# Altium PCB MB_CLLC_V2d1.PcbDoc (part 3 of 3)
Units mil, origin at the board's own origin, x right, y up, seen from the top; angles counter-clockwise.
Board outline 9000 x 7000 mil, 2 copper layers (Top Layer, Bottom Layer); 436 components, 223 nets, 1335 pads, 200 vias.
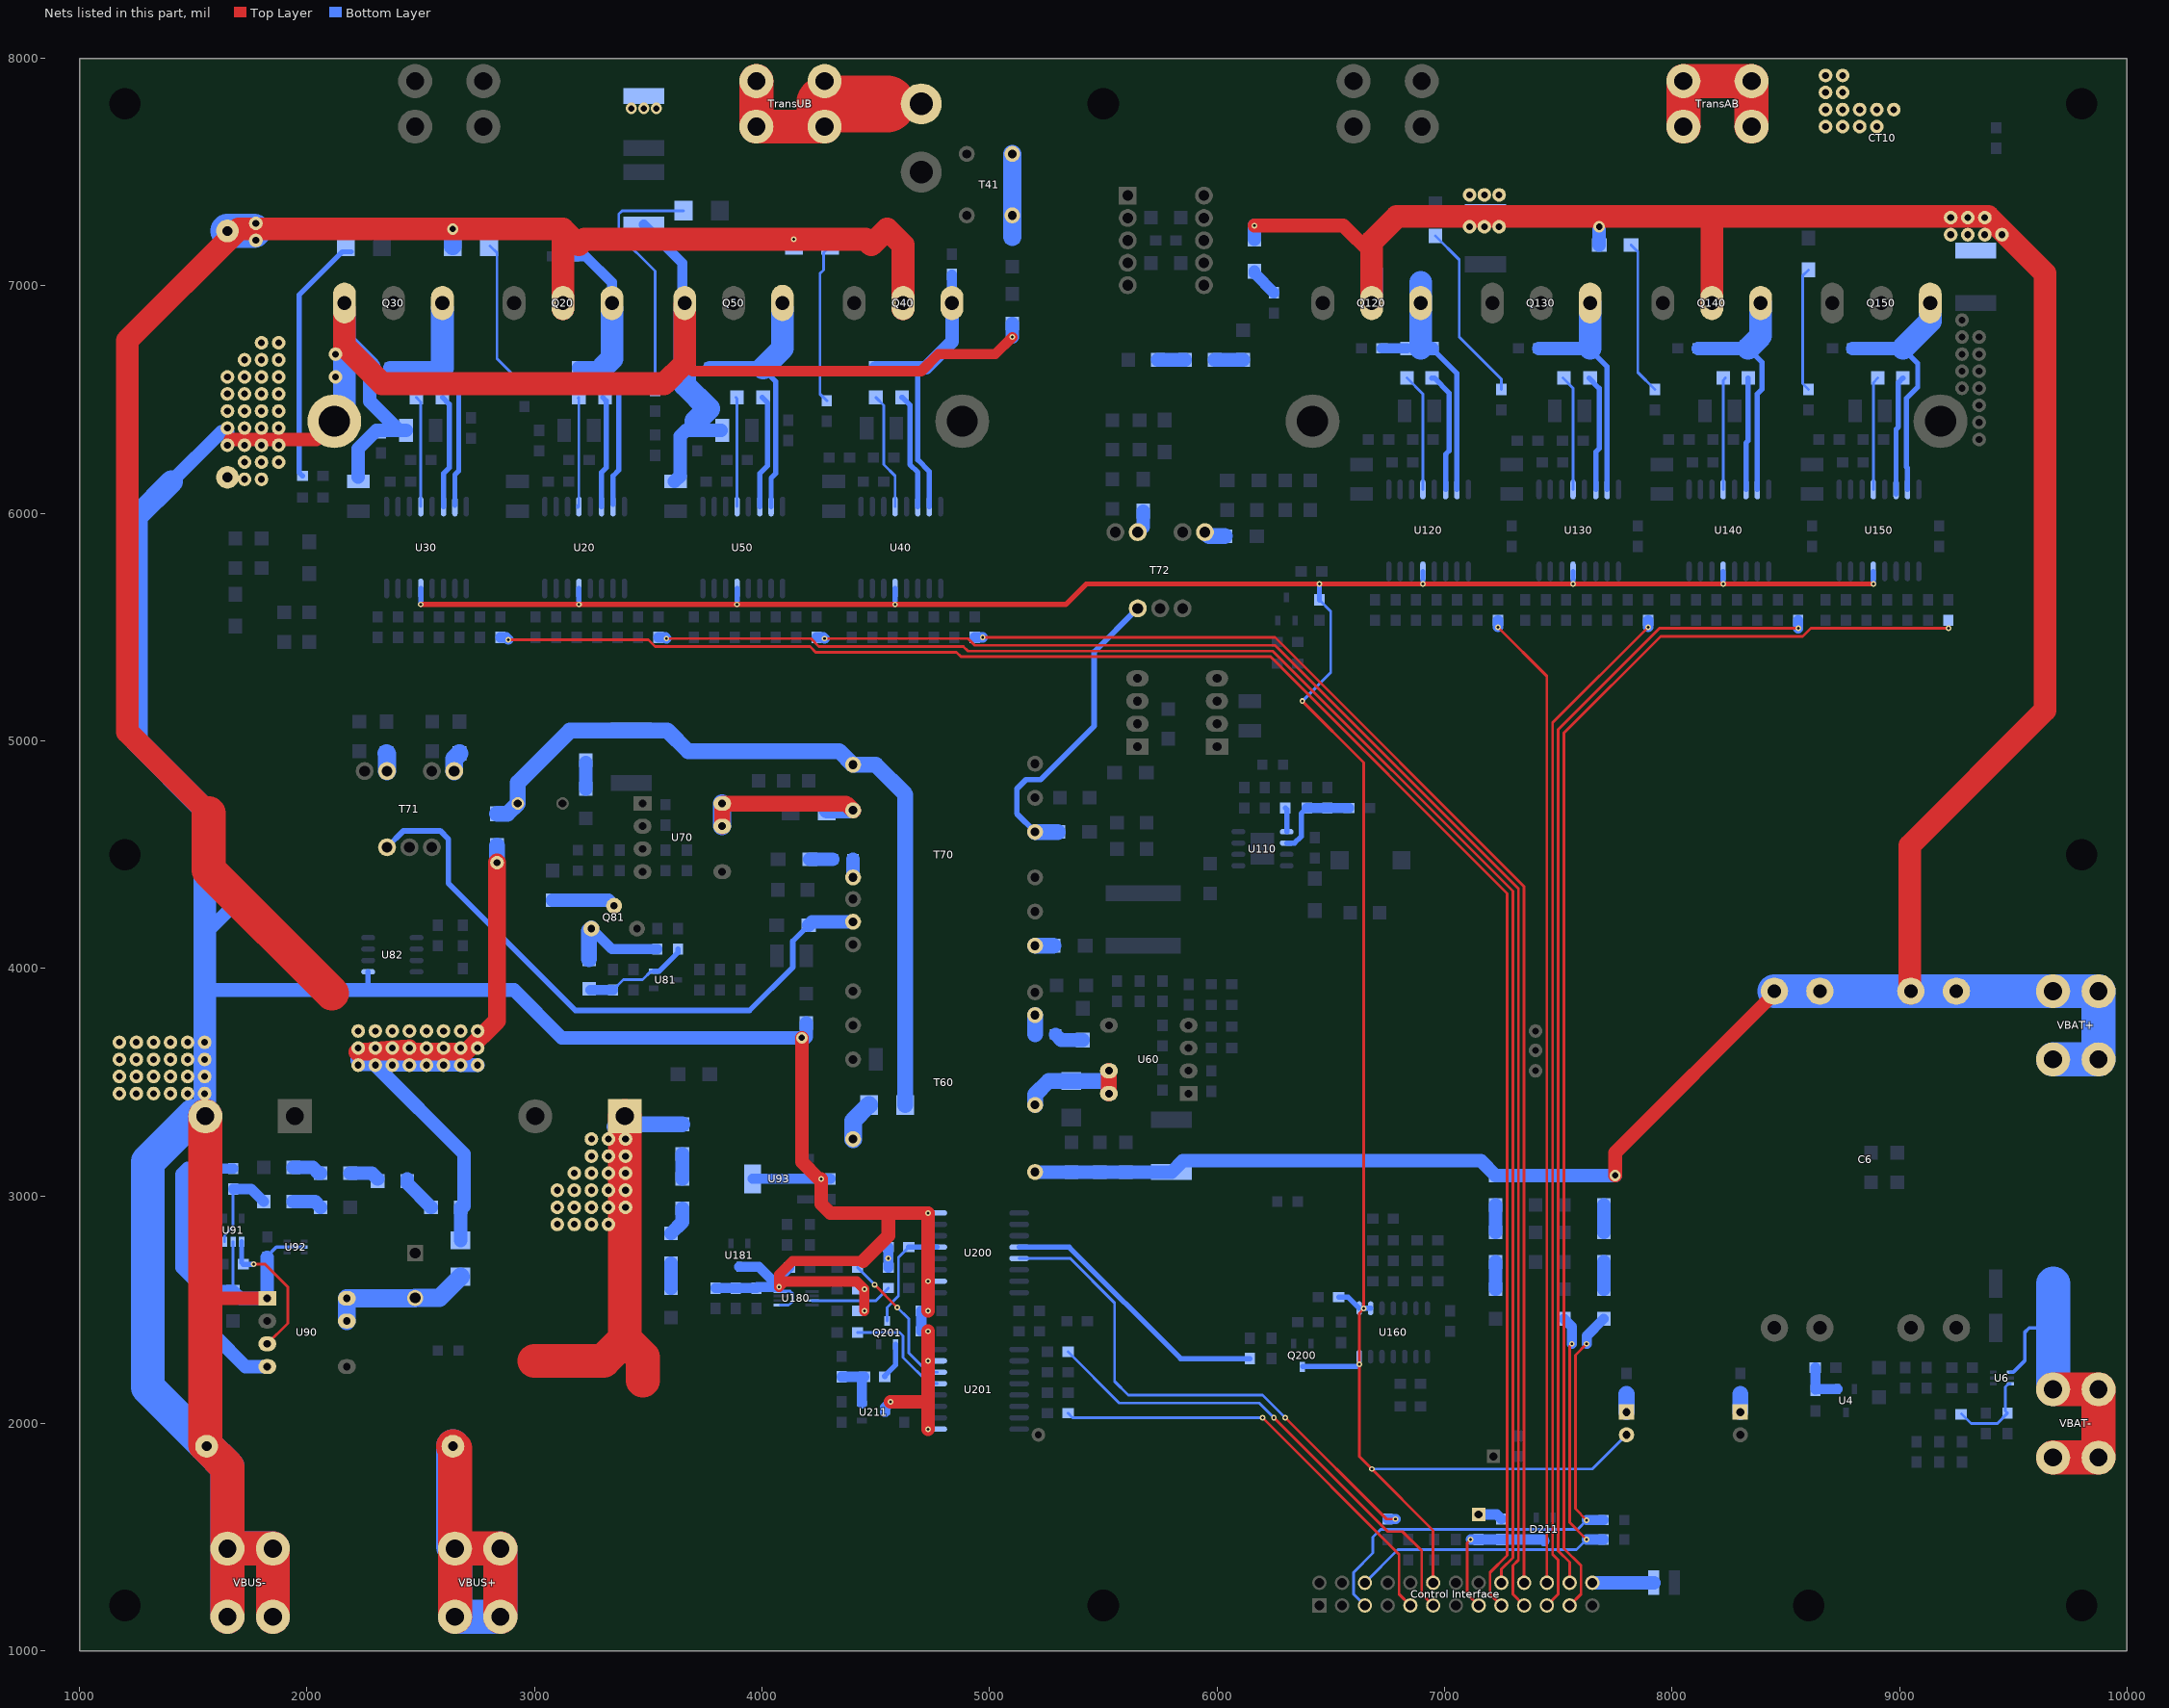
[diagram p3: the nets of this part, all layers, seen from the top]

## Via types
v1: diameter 25, hole 12, Top Layer to Bottom Layer, 169 vias
v2: diameter 50, hole 28, Top Layer to Bottom Layer, 31 vias

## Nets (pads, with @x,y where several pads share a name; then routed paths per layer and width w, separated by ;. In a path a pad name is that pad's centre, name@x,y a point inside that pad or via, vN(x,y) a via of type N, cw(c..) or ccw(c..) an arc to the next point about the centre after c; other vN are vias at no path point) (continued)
"NetControl Interface_5": "Control Interface.5" D191.1 R197.1 | length 2359.5
  Top Layer w12: v1(7625,1575) 7575,1625 7575,2300 v1(7625,2350)
  Bottom Layer w12: 6650,1200 6600,1250 6600,1345 6685,1430 6685,1500 6720,1535 7585,1535 v1(7625,1575)
  Bottom Layer w45: v1(7625,1575) D191.1@7700,1575 ; v1(7625,2350) 7625,2385 R197.1@7700,2460
"NetControl Interface_6": "Control Interface.6" D192.1 R262.1 | length 2148.4
  Top Layer w12: v1(7560,2350) 7550,2340 7550,1565 v1(7625,1490)
  Bottom Layer w12: 6650,1300 6795,1445 7580,1445 v1(7625,1490)
  Bottom Layer w45: R262.1@7525,2460 7560,2425 v1(7560,2350) ; v1(7625,1490) D192.1@7700,1490
"NetControl Interface_9": "Control Interface.9" R202.2 | length 1962.5
  Top Layer w12: v1(6200,2025) 6800,1425 6800,1250 6850,1200
  Bottom Layer w12: R202.2@5345,2045 5365,2025 v1(6200,2025) v1@6205,2025
"NetControl Interface_11": "Control Interface.11" R208.2 | length 2178.1
  Top Layer w12: v1(6250,2025) 6750,1525 6815,1525 6900,1440 6900,1250 6950,1200
  Bottom Layer w12: R208.2@5345,2315 5570,2090 6185,2090 v1(6250,2025)
"NetControl Interface_12": "Control Interface.12" Fault.2 Q200.3 R165.2 R172.2 U20.13 U30.13 U40.13 U50.13 U120.13 U130.13 U140.13 U150.13 U160.1 U160.2 U160.14 | length 13220.1
  Top Layer w12: v1(6375,5175) 6645,4905 v1(6645,2505) 6625,2485 v1(6625,2260) 6625,1855 v1(6680,1800) 6950,1530 6950,1300
  Top Layer w23: v1(2500,5600) v1(3195,5600) v1(3890,5600) v1(4585,5600) 5335,5600 5425,5690 v1(6450,5690) v1(6905,5690) v1(7565,5690) v1(8225,5690) v1(8885,5690)
  Bottom Layer w12: Q200.3@6375,2248.82 Q200.3@6376.18,2250 ; v1(6375,5175) 6500,5300 6500,5570 R165.2@6450,5620 ; v1(6680,1800) 7650,1800 Fault.2@7800,1950
  Bottom Layer w23: v1(2500,5600) U30.13@2500,5670 ; v1(3195,5600) U20.13@3195,5670 ; v1(3890,5600) U50.13@3890,5670 ; v1(4585,5600) U40.13@4585,5670 ; Q200.3@6376.18,2250 6615,2250 v1(6625,2260) ; R165.2@6450,5620 v1(6450,5690) ; R172.2@6535,2555 6576.3,2555 U160.1@6625,2506.3 ; v1@6641.3,2506.3 U160.2@6675,2506.3 ; v1(6905,5690) U120.13@6905,5745 ; v1(7565,5690) U130.13@7565,5745 ; v1(8225,5690) U140.13@8225,5745 ; v1(8885,5690) U150.13@8885,5745
"NetControl Interface_15": "Control Interface.15" D211.3 R217.1 R219.2 | length 644.5
  Top Layer w12: v1(7115,1490) 7100,1475 7100,1250 7150,1200
  Bottom Layer w45: v1(7115,1490) R217.1@7150,1490 R219.2@7250,1490 7433.82,1490 D211.3@7440,1483.82
"NetControl Interface_17": "Control Interface.17" R36.2 | length 8072.8
  Top Layer w12: v1(2885,5445) 3500,5445 3530,5415 4211,5415 4236,5390 4855,5390 4875,5370 6235,5370 7275,4330 7275,1420 7200,1345 7200,1250 7250,1200
  Bottom Layer w45: R36.2@2850,5455 2875,5455 v1(2885,5445)
"NetControl Interface_18": "Control Interface.18" R26.2 | length 7277.6
  Top Layer w12: v1(3580,5450) 4215,5450 4250,5415 4885,5415 4905,5395 6245,5395 7300,4340 7300,1410 7250,1360 7250,1300
  Bottom Layer w45: R26.2@3545,5455 3575,5455 v1(3580,5450)
"NetControl Interface_19": "Control Interface.19" R56.2 | length 6723.8
  Top Layer w12: v1(4275,5450) 4905,5450 4935,5420 6255,5420 7325,4350 7325,1400 7300,1375 7300,1250 7350,1200
  Bottom Layer w45: R56.2@4240,5455 4270,5455 v1(4275,5450)
"NetControl Interface_20": "Control Interface.20" R46.2 | length 5928.6
  Top Layer w12: v1(4970,5455) 6255,5455 7350,4360 7350,1300
  Bottom Layer w45: R46.2@4935,5455 v1(4970,5455)
"NetControl Interface_21": "Control Interface.21" R136.2 | length 4535
  Top Layer w12: 7450,1200 7500,1250 7500,1400 7475,1425 7475,5080 v1(7895,5500)
  Bottom Layer w45: v1(7895,5500) R136.2@7895,5530
"NetControl Interface_22": "Control Interface.22" R126.2 | length 4319.1
  Top Layer w12: v1(7235,5500) 7450,5285 7450,1300
  Bottom Layer w45: v1(7235,5500) R126.2@7235,5530
"NetControl Interface_23": "Control Interface.23" R156.2 | length 5767.3
  Top Layer w12: 7550,1200 7600,1250 7600,1375 7525,1450 7525,5035 7950,5460 8575,5460 8610,5495 v1(9215,5495)
"NetControl Interface_24": "Control Interface.24" R146.2 | length 5045
  Top Layer w12: 7550,1300 7550,1390 7500,1440 7500,5050 7945,5495 v1(8555,5495)
  Bottom Layer w45: v1(8555,5495) R146.2@8555,5530
"NetControl Interface_26": "Control Interface.26" L190.1 | length 270
  Bottom Layer w60: 7650,1300 L190.1@7920,1300
NetCT10_11: CT10.11 pad.47@8675,7700 pad.47@8675,7775 pad.47@8675,7850 pad.47@8675,7925 pad.47@8750,7700 pad.47@8750,7775 pad.47@8750,7850 pad.47@8750,7925 pad.47@8825,7700 pad.47@8825,7775 pad.47@8900,7700 pad.47@8900,7775 pad.47@8975,7775 TransAB.1 | length 700
  Top Layer w150: TransAB.1@8050,7700 TransAB.1@8050,7900 TransAB.1@8350,7900 TransAB.1@8350,7700
NetCT20_11: pad.CT20A TransUB.1 | length 875
  Top Layer w150: TransUB.1@3975,7900 TransUB.1@3975,7700 TransUB.1@4275,7700 4275,7800
  Top Layer w250: 4275,7800 4550,7800
NetD20_1: D20.1 R20.1 | length 677.1
  Bottom Layer w12: D20.1@2805,7175 2835,7145 2835,6680 R20.1@2955,6560
NetD30_1: D30.1 R30.1 | length 1109.9
  Bottom Layer w23: R30.1@1980,6165 1965,6180 1965,6960 2155,7150 D30.1@2195,7150
NetD40_1: D40.1 R40.1 | length 711.1
  Bottom Layer w12: R40.1@4285,6495 4255,6525 4255,7055 4270,7070 4270,7145 D40.1@4300,7175
NetD50_1: D50.1 R50.1 | length 1132.5
  Bottom Layer w12: R50.1@3530,6540 3530,7065 3370,7225 3370,7315 3385,7330 D50.1@3655,7330
NetD60_1: D60.1 T60.4 U60.6 U60.7 | length 594.9
  Top Layer w70: U60.7@5525,3450 U60.6@5525,3550
  Bottom Layer w70: T60.4@5200,3400 5200,3445 5260,3505 D60.1@5360,3505 5525,3505 ; U60.7@5525,3450 5525,3505 ; U60.6@5525,3550 5525,3505
NetD63_1: D63.1 R63.2 | length 130.4
  Bottom Layer w60: R63.2@5290,3710 5315,3685 D63.1@5410,3685
NetD66_1: D66.1 T60.13 | length 179
  Bottom Layer w78: T60.13@4400,3250 4400,3330 D66.1@4470,3400
NetD73_1: D73.1 T70.3 U70.6 U70.7 | length 902.4
  Top Layer w70: U70.6@3825,4625 U70.7@3825,4725 4370,4725 T70.3@4400,4695
  Bottom Layer w70: D73.1@4285,4695 T70.3@4400,4695
  Bottom Layer w80: U70.6@3825,4625 U70.7@3825,4725
NetD74_1: D74.1 R73.2 | length 100
  Bottom Layer w60: D74.1@4210,4480 R73.2@4310,4480
NetD75_1: D75.1 T70.9 | length 80
  Bottom Layer w70: T70.9@5200,4100 D75.1@5280,4100
NetD76_1: D76.1 T70.12 T72.2 | length 1373.9
  Bottom Layer w25: T70.12@5200,4600 5120,4680 5120,4790 5160,4830 5225,4830 5460,5065 5460,5390.91 T72.2@5651.57,5582.48
  Bottom Layer w70: T70.12@5200,4600 D76.1@5300,4600
NetD78_1: D78.1 T72.6 | length 95.4
  Bottom Layer w70: T72.6@5946.85,5917.52 5964.37,5900 D78.1@6035,5900
NetD80_1: D80.1 T72.9 | length 102.2
  Bottom Layer w60: T72.9@5651.57,5917.52 5675,5940.94 D80.1@5675,6010
NetD86_1: D86.1 T70.7 T71.2 | length 2748.7
  Bottom Layer w25: T71.2@2351.57,4532.48 2424.09,4605 2584.7,4605 2621.5,4568.19 2621.5,4373.5 3180,3815 3945,3815 4135,4005 4135,4120 D86.1@4205,4190
  Bottom Layer w60: D86.1@4205,4190 4220,4205 T70.7@4400,4205
NetD90_1: D90.1 L90.2 U90.6 U90.7 | length 639.4
  Bottom Layer w80: U90.6@2175,2450 U90.7@2175,2550 2473.43,2550 L90.2@2475,2551.57 2581.57,2551.57 D90.1@2675,2645
NetD100_1: D100.1 T71.6 | length 87.1
  Bottom Layer w80: T71.6@2646.85,4867.52 2646.85,4921.85 D100.1@2670,4945
NetD102_1: D102.1 T71.9 | length 78.1
  Bottom Layer w80: D102.1@2350,4945 2351.57,4943.43 T71.9@2351.57,4867.52
NetD120_1: D120.1 R120.1 | length 130.2
  Bottom Layer w50: D120.1@6165,7065 6165,7055 R120.1@6250,6970
NetD130_1: D130.1 R130.1 | length 795.1
  Bottom Layer w12: D130.1@6960,7220 7065,7115 7065,6775 7250,6590 R130.1@7250,6545
NetD140_1: D140.1 R140.1 | length 678.5
  Bottom Layer w12: D140.1@7820,7180 7850,7150 7850,6620 R140.1@7925,6545
NetD150_1: D150.1 R150.1 | length 545.7
  Bottom Layer w12: R150.1@8600,6545 8575,6570 8575,7045 D150.1@8600,7070
NetFault_1: Fault.1 R177.1 | length 80
  Bottom Layer w70: Fault.1@7800,2050 R177.1@7800,2130
NetPower_1: Power.1 R178.2 | length 80
  Bottom Layer w70: Power.1@8300,2050 R178.2@8300,2130
NetQ20_1: Q20.1 R21.2 R22.2 R23.2 U20.7 | length 1353.6
  Bottom Layer w23: R22.2@3300,6640 3370,6570 3370,6190 3345,6165 U20.7@3345,6040
  Bottom Layer w45: R23.2@3170,7130 3225,7130 3340,7015 Q20.1@3340,6925 Q20.1@3340,6900
  Bottom Layer w60: R21.2@3195,6640 R22.2@3300,6640
  Bottom Layer w100: R22.2@3300,6640 3340,6680 Q20.1@3340,6900
NetQ30_1: Q30.1 R31.2 R32.2 R33.2 U30.7 | length 1131.6
  Bottom Layer w23: R32.2@2595,6640 2666.69,6568.31 2666.69,6186.69 2650,6170 U30.7@2650,6035
  Bottom Layer w60: R33.2@2365,6640 R31.2@2480,6640 R32.2@2595,6640
  Bottom Layer w100: R32.2@2595,6640 Q30.1@2595,6900
NetQ40_1: Q40.1 R41.2 R42.2 R43.2 U40.7 | length 1308.3
  Bottom Layer w23: 4685,6640 4685,6235 4735,6185 U40.7@4735,6030
  Bottom Layer w45: Q40.1@4835,6900 Q40.1@4835,6925 R43.2@4835,7050
  Bottom Layer w60: R41.2@4500,6640 R42.2@4615,6640 4685,6640 4720,6640 4835,6755 Q40.1@4835,6900
NetQ50_1: Q50.1 R51.2 R52.2 R53.2 U50.7 | length 1168.3
  Bottom Layer w23: R52.2@4005,6635 4060,6580 4060,6175 4040,6155 U50.7@4040,6030
  Bottom Layer w60: R53.2@3770,6640 R51.2@3890,6640 4000,6640 R52.2@4005,6635
  Bottom Layer w100: R52.2@4005,6640 4090,6725 Q50.1@4090,6900
NetQ81_2: Q81.2 R71.1 | length 280.4
  Bottom Layer w60: R71.1@3080,4300 3325,4300 Q81.2@3350,4275
NetQ81_3: Q81.3 R82.1 R84.1 | length 466.4
  Bottom Layer w45: Q81.3@3250,4175 3340,4085 R82.1@3540,4085
  Bottom Layer w70: R84.1@3240,4040 3240,4165 Q81.3@3250,4175
NetQ120_1: Q120.1 R121.2 R122.2 R123.2 U120.7 | length 1115.6
  Bottom Layer w23: R122.2@6945,6725 7055,6615 U120.7@7055,6105
  Bottom Layer w45: R123.2@6725,6725 R121.2@6835,6725
  Bottom Layer w60: 6895,6725 R122.2@6945,6725
  Bottom Layer w100: 6895,6725 Q120.1@6895,6925 6895,7015
NetQ130_1: Q130.1 R131.2 R132.2 R133.2 U130.7 | length 1078.1
  Bottom Layer w23: R132.2@7635,6725 7715,6645 U130.7@7715,6105
  Bottom Layer w60: R133.2@7415,6725 R131.2@7525,6725 7635,6725 R132.2@7640,6725
  Bottom Layer w100: R132.2@7640,6725 Q130.1@7640,6925
NetQ140_1: Q140.1 R141.2 R142.2 R143.2 U140.7 | length 1095.9
  Bottom Layer w23: R142.2@8335,6725 8395,6665 8395,6545 8375,6525 U140.7@8375,6105
  Bottom Layer w60: R143.2@8115,6725 R141.2@8225,6725 R142.2@8335,6725
  Bottom Layer w100: R142.2@8335,6725 8390,6780 Q140.1@8390,6925
NetQ150_1: Q150.1 R151.2 R152.2 R153.2 U150.7 | length 1139.4
  Bottom Layer w23: R152.2@9015,6725 9080,6660 9080,6555 9030,6505 9030,6205 9035,6200 U150.7@9035,6105
  Bottom Layer w60: R153.2@8795,6725 R151.2@8905,6725 R152.2@9015,6725
  Bottom Layer w100: R152.2@9015,6725 9135,6845 Q150.1@9135,6925
NetQ201_1: Q201.1 R212.2 | length 164.4
  Bottom Layer w23: R212.2@4540,2205 4537.4,2207.6 4587.4,2257.6 Q201.1@4587.4,2347.64
NetQ201_3: Q201.3 R209.1 U200.5 | length 489.4
  Bottom Layer w12: Q201.3@4550,2450 4550,2510 4600,2560 4600,2730 R209.1@4645,2775
  Bottom Layer w23: R209.1@4645,2775 U200.5@4770,2775
NetR5_2: R5.2 R6.1 U4.1 | length 193.1
  Bottom Layer w45: R5.2@8630,2245 8630,2150 8631.18,2151.18 U4.1@8727.6,2151.18
NetR12_1: R12.1 R13.2 | length 125
  Bottom Layer w60: R13.2@5990,6675 R12.1@6115,6675
NetR13_1: R13.1 R14.2 | length 120
  Bottom Layer w60: R14.2@5740,6675 R13.1@5860,6675
NetR21_1: R21.1 U20.4 | length 500.4
  Bottom Layer w12: U20.4@3190,6025 3190,6035 U20.4@3195,6030 3195,6502 3191,6506 R21.1@3195,6510
NetR22_1: R22.1 U20.6 | length 494.5
  Bottom Layer w23: U20.6@3295,6030 3295,6180 3315,6200 3315,6495 R22.1@3300,6510
NetR31_1: R31.1 U30.4 | length 488.3
  Bottom Layer w12: R31.1@2480,6510 2500,6490 U30.4@2500,6030
NetR32_1: R32.1 U30.6 | length 502.8
  Bottom Layer w23: R32.1@2595,6510 2625,6480 2625,6200 2600,6175 U30.6@2600,6030
NetR41_1: R41.1 U40.4 | length 515.2
  Bottom Layer w12: R41.1@4500,6510 4535,6475 4535,6215 4585,6165 U40.4@4585,6030
NetR42_1: R42.1 U40.6 | length 509.9
  Bottom Layer w23: R42.1@4615,6510 4616.5,6510 4650,6476.5 4650,6215 4685,6180 U40.6@4685,6030
NetR51_1: R51.1 U50.4 | length 482.1
  Bottom Layer w12: R51.1@3885,6510 3890,6505 U50.4@3890,6030
NetR52_1: R52.1 U50.6 | length 504.9
  Bottom Layer w23: U50.6@3990,6030 3990,6175 4025,6210 4025,6485 R52.1@4000,6510
NetR63_1: R63.1 T60.7 | length 85
  Bottom Layer w70: R63.1@5200,3710 T60.7@5200,3795
NetR73_1: R73.1 T70.5 | length 80
  Bottom Layer w60: T70.5@4400,4400 R73.1@4400,4480
NetR83_1: R83.1 R84.2 R85.1 U81.2 | length 475.4
  Bottom Layer w12: R84.2@3240,3910 R84.2@3245,3905 ; R85.1@3345,3905 3390,3950 3475,3950 3512.4,3987.4 U81.2@3523.82,3987.4
  Bottom Layer w23: U81.2@3523.82,3987.4 3547.4,3987.4 3630,4070 R83.1@3630,4085
  Bottom Layer w45: R84.2@3245,3905 R85.1@3345,3905
NetR90_1: R90.1 U90.3 U91.1 | length 625.7
  Top Layer w12: v1(1765,2700) 1815,2700 1915,2600 1915,2440 U90.3@1825,2350
  Bottom Layer w23: U91.1@1712.4,2798.82 1712.4,2707.6 R90.1@1720,2700 v1(1765,2700)
NetR92_1: R92.1 R93.1 U91.3 | length 404.5
  Bottom Layer w12: U91.3@1637.6,2798.82 1637.6,2827.6 1675,2865 R92.1@1675,3030
  Bottom Layer w45: R92.1@1675,3030 1755,3030 R93.1@1810,2975
NetR93_2: R93.2 R94.1 | length 130.4
  Bottom Layer w60: R93.2@1940,2975 2035,2975 R94.1@2060,2950
NetR95_2: R95.2 R96.1 | length 130.4
  Bottom Layer w60: R95.2@1940,3125 2025,3125 2050,3100 R96.1@2060,3100
NetR96_2: R96.2 R97.1 | length 130.4
  Bottom Layer w60: R96.2@2190,3100 2285,3100 R97.1@2310,3075
NetR97_2: R97.2 R98.1 | length 168.5
  Bottom Layer w60: R97.2@2440,3075 R97.2@2440,3065 2440,3055 R98.1@2545,2950
NetR105_1: R105.1 R106.2 | length 115
  Bottom Layer w60: R106.2@3225,4790 R105.1@3225,4905
NetR110_1: R110.1 U110.5 | length 106.6
  Bottom Layer w23: R110.1@6300,4705 6306.3,4698.7 U110.5@6306.3,4601
NetR111_1: R111.1 R112.1 R113.2 U110.6 | length 396.1
  Bottom Layer w23: U110.6@6306.3,4551 6341,4551 6370,4580 6370,4680 R112.1@6395,4705
  Bottom Layer w45: R112.1@6395,4705 R111.1@6485,4705 R113.2@6580,4705
NetR121_1: R121.1 U120.4 | length 519
  Bottom Layer w12: R121.1@6835,6595 6905,6525 U120.4@6905,6105
NetR122_1: R122.1 U120.6 | length 533.1
  Bottom Layer w23: R122.1@6945,6595 6955,6595 7020,6530 7020,6275 7005,6260 U120.6@7005,6105
NetR131_1: R131.1 U130.4 | length 508.6
  Bottom Layer w12: R131.1@7520,6595 7565,6550 U130.4@7565,6105
NetR132_1: R132.1 U130.6 | length 514.9
  Bottom Layer w23: R132.1@7635,6595 7680,6550 7680,6285 7665,6270 U130.6@7665,6105
NetR141_1: R141.1 U140.4 | length 494.1
  Bottom Layer w12: U140.4@8225,6105 8225,6585 R141.1@8235,6595
NetR142_1: R142.1 U140.6 | length 494.1
  Bottom Layer w23: U140.6@8325,6105 8325,6310 8335,6320 R142.1@8335,6595
NetR151_1: R151.1 U150.4 | length 498.3
  Bottom Layer w12: U150.4@8885,6105 8885,6575 R151.1@8905,6595
NetR152_1: R152.1 U150.6 | length 522.4
  Bottom Layer w23: U150.6@8985,6085 U150.6@8985,6105 8985,6370 8995,6380 8995,6575 R152.1@9015,6595
NetR169_1: R169.1 R193.1 U6.6 | length 386.2
  Bottom Layer w12: R169.1@9272.5,2042.5 9315,2000 9430,2000 R193.1@9475,2045 9465,2055 9465,2160 9479,2174 U6.6@9487.5,2174
NetR180_1: R180.1 R181.2 | length 110
  Bottom Layer w60: R181.2@3650,3075 R180.1@3650,3185
NetR181_1: R181.1 R182.2 | length 130.7
  Bottom Layer w60: R182.2@3600,2835 3650,2885 R181.1@3650,2945
NetR182_1: R182.1 R183.2 | length 110
  Bottom Layer w60: R183.2@3600,2595 R182.1@3600,2705
NetR187_2: R187.2 U201.13 | length 498.8
  Bottom Layer w12: R187.2@4420,2400 4605,2400 4620,2385 4620,2290 4735,2175 U201.13@4770,2175
NetR188_2: R188.2 U201.14 | length 628.4
  Top Layer w12: v1(4495,2610) v1(4595,2510)
  Bottom Layer w12: R188.2@4420,2685 v1(4495,2610) ; v1(4595,2510) 4645,2460 4645,2310 4730,2225 U201.14@4770,2225
NetR195_1: R195.1 R196.2 | length 120
  Bottom Layer w60: R196.2@7700,2840 R195.1@7700,2960
NetR196_1: R196.1 R197.2 | length 120
  Bottom Layer w60: R197.2@7700,2590 R196.1@7700,2710
NetR200_1: R200.1 U200.12 | length 1218
  Bottom Layer w23: U200.12@5130,2775 5350,2775 5840,2285 R200.1@6145,2285
NetR203_1: R203.1 U180.3 | length 357.8
  Bottom Layer w12: U180.3@4220,2540 4500,2540 R203.1@4555,2595
NetR205_1: R205.1 U200.13 | length 2366.4
  Top Layer w12: v1(6300,2025) 6745,1580 v1(6785,1580)
  Bottom Layer w12: U200.13@5130,2725 5355,2725 5550,2530 5550,2185 5610,2125 6200,2125 v1(6300,2025)
  Bottom Layer w45: R205.1@6750,1580 v1(6785,1580)
NetR211_2: R211.2 R212.1 U211.2 | length 222.2
  Bottom Layer w45: R211.2@4350,2205 R212.1@4450,2205 4438.82,2193.82 U211.2@4438.82,2087.4
NetR213_2: R213.2 T41.1 | length 365
  Bottom Layer w80: R213.2@5100,7215 T41.1@5100,7310 T41.1@5100,7580
NetR219_1: R219.1 T41+.1 | length 108.3
  Bottom Layer w45: T41+.1@7150,1600 7230,1600 R219.1@7250,1580
NetR230_1: R230.1 R231.1 U6.4 VBAT-.1 | length 1506.1
  Top Layer w150: VBAT-.1@9675,1850 VBAT-.1@9875,1850 VBAT-.1@9875,2150 VBAT-.1@9675,2150
  Bottom Layer w15: U6.4@9487.5,2226 9501,2226 9550,2275 9550,2400 9570,2420 R231.1@9675,2420
  Bottom Layer w150: VBAT-.1@9675,2150 R231.1@9675,2420 R230.1@9675,2615
NetR250_1: R250.1 R251.2 | length 120
  Bottom Layer w60: R251.2@7225,2840 R250.1@7225,2960
NetR251_1: R251.1 R252.2 | length 120
  Bottom Layer w60: R252.2@7225,2590 R251.1@7225,2710
PGND: C1.1 C3.2 C10.1 C30.2 C33.2 C50.2 C53.2 C87.2 C90.1 C91.1 C93.1 C180.1 C181.1 C182.1 C183.1 C184.1 C203.1 C205.1 C206.1 C210.1 C214.1 C229.1 HS1.2 pad.7@1175,3450 pad.7@1175,3525 pad.7@1175,3600 pad.7@1175,3675 pad.7@1250,3450 pad.7@1250,3525 pad.7@1250,3600 pad.7@1250,3675 pad.7@1325,3450 pad.7@1325,3525 pad.7@1325,3600 pad.7@1325,3675 pad.7@1400,3450 pad.7@1400,3525 pad.7@1400,3600 pad.7@1400,3675 pad.7@1475,3450 pad.7@1475,3525 pad.7@1475,3600 pad.7@1475,3675 pad.7@1550,3450 pad.7@1550,3525 pad.7@1550,3600 pad.7@1550,3675 pad.10 pad.11 pad.12 pad.13 pad.14 pad.15 pad.16 pad.17 pad.18 pad.19 pad.20 pad.21 pad.22 pad.28 pad.29 pad.30 pad.31 pad.32 pad.33 pad.34 pad.35 pad.36@1800,6750 Q30.3 Q50.3 R33.1 R34.1 R53.1 R54.1 R88.1 R91.2 R92.2 R184.2 R209.2 U82.1 U90.1 U90.4 U91.2 U92.2 U93.2 U93.4 U180.5 U180.8 U181.3 U200.2 U200.8 U201.9 U201.15 U211.3 VBUS-.1 | length 26186.7
  Top Layer w45: 3660,6660 3695,6625 4700,6625 4775,6700 5025,6700 v1(5100,6775) ; 4443.82,2713.82 4134.77,2713.82 4075,2654.05 v1(4075,2600) 4098.82,2623.82 4416.18,2623.82 v1(4450,2590) v1(4450,2495)
  Top Layer w60: 1553.15,2550 U90.1@1825,2550 ; pad.13@1665,6325 2040,6325 HS1.2@2120,6405 ; v2(4175,3695) 4175,3150 4250,3075 v1(4260,3075) 4260,2965 4300,2925 v1(4730,2925) v1(4730,2625) v1(4730,2495) ; 4443.82,2713.82 4555,2825 4555,2915 ; v1(4565,2095) 4730,2095 ; v1(4730,1975) 4730,2095 ; v1(4730,2405) v1(4730,2275) 4730,2095
  Top Layer w100: Q30.3@2165,6900 2165,6735 2330,6570 3570,6570 3660,6660 Q50.3@3660,6915
  Top Layer w150: C3.2@1553.15,3350 1553.15,2550 1553.15,1905.51 C1.1@1558.66,1900 1650,1808.66 VBUS-.1@1650,1450 ; VBUS-.1@1650,1150 VBUS-.1@1650,1450 ; VBUS-.1@1850,1150 VBUS-.1@1850,1450 VBUS-.1@1650,1450
  Bottom Layer w11.8: U180.5@4080,2520 4116.4,2520 4135,2535 4135,2570 4123.2,2581.8 U180.8@4080,2581.8
  Bottom Layer w12: C90.1@1675,2580 U91.2@1675,2798.82
  Bottom Layer w15: C91.1@1825,2730 1825,2735 1865,2775 U92.2@1987.5,2775
  Bottom Layer w23: U82.1@2268.7,3985 2268.7,3931.3 2295,3905
  Bottom Layer w45: R91.2@1545,3120 R92.2@1675,3120 ; C229.1@3480,7270 3650,7100 3650,6935 Q50.3@3660,6925 ; R184.2@3795,2595 C180.1@3885,2595 C181.1@3975,2595 3980,2600 v1(4075,2600) ; U181.3@3900,2688.82 3986.18,2688.82 v1(4075,2600) ; U93.4@3958.86,3075 U93.2@4191.14,3075 v1(4260,3075) C93.1@4300,3075 ; C182.1@4120,2685 4075,2640 v1(4075,2600) ; U211.3@4541.18,2050 4541.18,2071.18 v1(4565,2095) C210.1@4625,2095 ; C205.1@4555,2685 v1(4555,2725) R209.2@4555,2775 ; C206.1@4700,2405 C203.1@4700,2495
  Bottom Layer w60: 1405,6140 1623.66,6358.66 pad.13@1650,6358.66 ; R91.2@1545,3120 1475,3120 1450,3095 1450,2685 1555,2580 1595,2580 ; 1550,3905 2295,3905 2910,3905 3120,3695 v2(4175,3695) 4190,3695 4195,3700 C87.2@4195,3760 ; 1550,4150 1640,4240 ; U90.4@1825,2250 1730,2250 1595,2385 1595,2580 ; C91.1@1825,2730 U90.1@1825,2550 1705,2550 C90.1@1675,2580 1595,2580 ; C33.2@2225,6160 2225,6285 2305,6365 2403.11,6365 ; R33.1@2275,6640 2275,6493.11 2403.11,6365 ; C30.2@2435,6365 2403.11,6365 ; C53.2@3615,6140 3640,6165 3640,6340 3665,6365 R54.1@3710,6365 ; 3710,6405 R54.1@3710,6365 ; C50.2@3820,6365 R54.1@3715,6365 R54.1@3710,6365 ; v1(5100,6775) C214.1@5100,6835
  Bottom Layer w100: 1405,6140 1250,5985 1250,5000 1550,4700 1550,4150 1550,3910 ; C3.2@1550,3350 pad.7@1550,3450 pad.7@1550,3525 pad.7@1550,3600 pad.7@1550,3675 1550,3905 ; HS1.2@2120,6405 2165,6450 2165,6750 ; Q30.3@2165,6900 2165,6750 ; R33.1@2275,6640 2165,6750 ; Q50.3@3660,6900 3660,6565 3765,6460 3710,6405
  Bottom Layer w150: C3.2@1553.15,3350 1550,3350 1500,3350 1300,3150 1300,2158.66 C1.1@1558.66,1900 1650,1808.66 VBUS-.1@1650,1450 ; VBUS-.1@1650,1150 VBUS-.1@1650,1450 ; VBUS-.1@1850,1150 VBUS-.1@1850,1450 VBUS-.1@1650,1450
VBAT: C6.1 C60.2 C68.2 C128.2 C148.2 C260.2 D120.2 D140.2 pad.37 pad.38 pad.39 pad.40 pad.41 pad.42 pad.43 pad.44 pad.45 pad.46 pad.47@9225,7300 pad.48 pad.49 pad.56@8450,3900 pad.56@9250,3900 Q120.2 Q140.2 R60.2 R61.2 R195.2 R250.2 R260.2 T60.1 VBAT+.1 | length 13642
  Top Layer w60: v1(6165,7265) 6555,7265 6680,7140 ; v2(7750,3090) 7750,3190 8450,3890 pad.56@8450,3900
  Top Layer w100: Q120.2@6680,6925 6680,7140 6680,7195 6790,7305 8175,7305 ; Q140.2@8175,6925 8175,7305 ; C6.1@9050,3890 9045,3895 9045,4540 9640,5135 9640,7055 9390,7305 8175,7305
  Bottom Layer w60: T60.1@5200,3105 C60.2@5360,3105 R60.2@5485,3105 R61.2@5600,3105 C68.2@5800,3105 5850,3155 7160,3155 R250.2@7225,3090 C260.2@7400,3090 R260.2@7525,3090 7625,3090 ; D120.2@6165,7205 v1(6165,7265) ; 7630,3090 R195.2@7700,3090 v2(7750,3090) ; D140.2@7680,7180 v2(7680,7260)
  Bottom Layer w100: Q120.2@6680,6925 6680,7070
  Bottom Layer w150: pad.56@8450,3900 C6.1@8650,3900 C6.1@9050,3900 pad.56@9250,3900 VBAT+.1@9675,3900 VBAT+.1@9875,3900 VBAT+.1@9875,3600 VBAT+.1@9675,3600
VBUS: C1.2 C2.1 C10.2 C129.2 D20.2 D40.2 D90.2 D99.1 pad.3 pad.4 pad.5 pad.6 pad.7@2225,3575 pad.7@2225,3650 pad.7@2225,3725 pad.7@2300,3575 pad.7@2300,3650 pad.7@2300,3725 pad.7@2375,3575 pad.7@2375,3650 pad.7@2375,3725 pad.7@2450,3575 pad.7@2450,3650 pad.7@2450,3725 pad.7@2525,3650 pad.7@2525,3725 pad.7@2600,3650 pad.7@2600,3725 pad.7@2675,3650 pad.7@2675,3725 pad.7@2750,3575 pad.7@2750,3650 pad.7@2750,3725 pad.8@3100,2875 pad.8@3100,2950 pad.8@3100,3025 pad.8@3175,2875 pad.8@3175,2950 pad.8@3175,3025 pad.8@3175,3100 pad.8@3250,2875 pad.8@3250,2950 pad.8@3250,3025 pad.8@3250,3100 pad.8@3250,3175 pad.8@3250,3250 pad.8@3325,2875 pad.8@3325,2950 pad.8@3325,3025 pad.8@3325,3100 pad.8@3325,3175 pad.8@3325,3250 pad.8@3400,2950 pad.8@3400,3025 pad.8@3400,3100 pad.8@3400,3175 pad.8@3400,3250 pad.36@1775,7200 pad.36@1775,7275 Q20.2 Q40.2 R98.2 R180.2 VBUS+.1 | length 15627.9
  Top Layer w78: pad.7@2220.62,3632.56 2226.29,3632.99 2252.73,3635 ; pad.7@2450,3650 2375.43,3644.33 2300.86,3638.66 2295.19,3638.23 2252.73,3635 ; pad.3@2835,4465 2835,3770 2700,3635 2450,3635 2252.73,3635
  Top Layer w100: 1567.5,4682.5 1210,5040 1210,6760 1700,7250 v2(2640,7250) 3125,7250 ; Q20.2@3125,6900 Q20.2@3125,6925 3125,7250 ; Q40.2@4620,6900 Q40.2@4620,6925 4620,7180 4550,7250 4480,7180 4455,7205 v1(4140,7205) 3220,7205 3195,7180 3125,7250
  Top Layer w150: 1567.5,4682.5 1567.5,4432.5 2110,3890 ; C1.2@2641.34,1900 2650,1891.34 VBUS+.1@2650,1450 ; VBUS+.1@2650,1150 VBUS+.1@2650,1450 ; VBUS+.1@2850,1150 VBUS+.1@2850,1450 VBUS+.1@2650,1450 ; 3000,2275 3301.7,2275 3396.85,2370.15 ; C2.1@3396.85,3350 3396.85,2950 3396.85,2370.15 ; 3477,2190 3477,2290 3396.85,2370.15
  Bottom Layer w25: D40.2@4140,7180 v1(4140,7205)
  Bottom Layer w60: pad.7@2219.92,3597.1 pad.7@2236.3,3600.86 ; pad.7@2220.24,3594.79 pad.7@2237.28,3598.89 ; pad.7@2222.06,3621.17 pad.7@2226.82,3621.47 ; pad.7@2222.86,3604.16 2228.33,3604.56 2263.66,3607.15 ; pad.7@2225.02,3578.38 pad.7@2297.09,3577.91 ; 2251.93,3623.07 2296.76,3625.93 pad.7@2301.51,3626.23 ; 2291.15,3613.47 2307.53,3617.24 ; 2308.19,3615.92 2291.15,3611.83 2268.59,3606.41 2267.56,3607.44 ; pad.7@2362.06,3628.87 pad.7@2368.93,3630.52 ; pad.7@2362.39,3629.85 pad.7@2363.88,3630.2 ; pad.7@2376.21,3630.98 2371.46,3630.68 pad.7@2368.93,3630.52 ; pad.7@2378.77,3633.62 pad.7@2363.88,3630.2 ; pad.7@2379.09,3632.96 pad.7@2368.93,3630.52 ; D90.2@2675,2805 R98.2@2675,2950 ; R98.2@2690,2955 2690,3185 pad.7@2300,3575 pad.7@2297.09,3577.91 ; pad.7@2750,3575 2675,3575.48 2600.01,3575.96 2525.01,3576.45 2450.01,3576.93 2375.02,3577.41 2300.02,3577.89 pad.7@2297.09,3577.91 ; C2.1@3346.37,3304.46 3348.46,3302.34 3363.08,3287.5 pad.8@3400,3250 ; 2263.66,3607.15 2267.56,3607.44 ; 2263.66,3607.15 2267.06,3607.94 2267.56,3607.44 ; pad.7@2363.88,3630.2 pad.7@2368.93,3630.52
  Bottom Layer w70: pad.3@2835,4465 D99.1@2835,4540 ; C2.1@3396.85,3350 3431.85,3315 R180.2@3650,3315
  Bottom Layer w78: D20.2@2640,7175 v2(2640,7250)
  Bottom Layer w150: C10.2@1650,7241.34 1766.34,7241.34 ; C1.2@2641.34,1900 2641.34,1458.66 VBUS+.1@2650,1450 VBUS+.1@2650,1150 VBUS+.1@2850,1150 VBUS+.1@2850,1450
  other v2: 3425,7780 3480,7780 3535,7780
VBUS-: C67.2 C75.2 C98.2 C99.2 D66.2 D99.2 R74.2 R75.2 R105.2 T70.1 | length 3480.8
  Bottom Layer w70: D99.2@2835,4680 2881.57,4680 C98.2@2926.57,4725 2926.57,4816.57 3155,5045 R105.2@3225,5045 C99.2@3425,5045 3585,5045 3675,4955 R75.2@3985,4955 R74.2@4095,4955 C75.2@4205,4955 4340,4955 T70.1@4400,4895 4500,4895 4630,4765 C67.2@4630,3600 D66.2@4630,3400
pads on no net: "Control Interface.13" CT10.1 CT10.3 CT10.5 CT10.7 FAN1.4 FAN2.4 H8.1 H9.1 H10.1 H11.1 H12.1 H13.1 H14.1 H15.1 H16.1 HS1.1 HS2.2 T60.2 T60.3 T60.5 T60.6 T60.9 T60.10 T60.12 T60.14 T70.2 T70.4 T70.11 T70.14 T71.1 T71.4 T71.5 T71.8 T72.1 T72.4 T72.5 T72.8 U20.12 U20.14 U30.12 U30.14 U40.12 U40.14 U50.12 U50.14 U92.1 U92.3 U120.12 U120.14 U130.12 U130.14 U140.12 U140.14 U150.12 U150.14 U160.10 U160.11 U160.13 U200.3 U200.6 U200.7 U200.10 U200.11 U200.14 U201.5 U201.6 U201.7 U201.10 U201.11 U201.12

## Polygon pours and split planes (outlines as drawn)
GND on Top Layer "Bottom Layer-No Net 6" (solid, pour order 73): 7100,2950 7175,2875 7175,1900 7100,1825 6625,1825 6195,2255 6195,2870 6275,2950
PGND on Top Layer "Bottom Layer-No Net 6" (solid, pour order 64): 4500,3000 4700,3000 4755,2945 4755,1980 4650,1875 4000,1875 3750,2125 3750,3125 3875,3250 4100,3250 4175,3325
GND on Top Layer "Bottom Layer-No Net 6" (solid, pour order 71): 5125,2975 5100,2950 5100,1860 5110,1850 5325,1850 5475,2000 5475,2900 5400,2975
C_BU_B on Top Layer "Bottom Layer-No Net 6" (solid, pour order 68): 4950,7550 4950,7600 4925,7625 4800,7625 4775,7600 4575,7600 4550,7575 4550,7500 4775,7275 4925,7275 4950,7300
NetCT20_11 on Top Layer "Bottom Layer-No Net 6" (solid, pour order 66): 3900,7975 3850,7925 3850,7700 3925,7625 4750,7625 4825,7700 4825,7900 4750,7975
Half-BUS on Top Layer "Top Layer-No Net 2" (solid, pour order 50): 1865,3425 1825,3385 1825,3200 2325,2700 2525,2700 3100,3275 3100,3500 3000,3600 2825,3425
VBUS on Top Layer "Top Layer-No Net 2" (solid, pour order 48): 2625,2375 2250,2000 2250,1150 2375,1025 3025,1025 3250,1250 3250,1825 3550,2125 3550,2925 3625,3000 3625,3375 3550,3450 3275,3450 3200,3375 3200,3225 2625,2650
PGND on Top Layer "Top Layer-No Net 2" (solid, pour order 44): 1975,1025 2025,1075 2025,1900 1750,2175 1750,2475 1825,2550 1825,2575 1725,2675 1725,3700 1450,3975 1125,3975 1025,3875 1025,1750 1450,1325 1450,1075 1500,1025
PGND on Top Layer "Top Layer-No Net" (solid, pour order 0): 1575,6325 1575,6100 1625,6050 1775,6050 2010,6285 2023.65,6285 2430,6285 2545,6400 4025,6400 4250,6625 4150,6725 3800,6725 3715,6810 3715,6985 3675,7025 3550,7025 3500,6975 3500,6800 3425,6725 2300,6725 2225,6800 2225,7000 2200,7025 2025,7025 1575,6575
VBUS on Top Layer "Top Layer-No Net" (solid, pour order 2): 2950,7500 3275,7825 3555,7825 3880,7500 4385,7500 4685,7200 4685,6830 4660,6805 4660,6795 4585,6795 4555,6825 4555,7035 4465,7125 3280,7125 3190,7035 3190,6850 3165,6825 3090,6825 3065,6850 3065,7035 2975,7125 1975,7125 1475,6625 1475,6165 1475,5420 1975,4920 1975,4505 2305,4175 2375,4175 2700,4175 2825,4300 2875,4300 2875,3625 2775,3525 2175,3525 1400,4300 1400,4400 1400,4625 1025,5000 1025,7525 1100,7600 2225,7600 2325,7500
VBAT on Top Layer "Top Layer-No Net 1" (solid, pour order 20): 6624.99,6850.01 6600,6875 6600,7250 6825,7475 9600,7475 9925,7150 9925,4975 9575,4625 9575,4350 9975,3950 9975,3525 9925,3475 8720,3475 8375,3820 8375,4425 9500,5550 9500,6825 9225,7100 8325,7100 8250,7025 8250,6875 8225.01,6850.01 8124.99,6850.01 8100,6875 8100,7025 7975,7150 6875,7150 6750,7025 6750,6875 6725.01,6850.01
GND on Top Layer "Top Layer-No Net 1" (solid, pour order 40): 7260,7015 7065,7015 7025,6975 7025,6575 7225,6375 8905,6375 9035,6245 9335,6245 9400,6310 9400,6800 9310,6890 9265,6890 9150,6775 8850,6775 8775,6850 8775,6975 8735,7015 8590,7015 8525,6950 8525,6825 8450,6750 7370,6750 7300,6820 7300,6975
NetD60_1 on Top Layer "Top Layer-No Net 3" (solid, pour order 75): 5150,3375 5150,3525 5225,3600 5545,3600 5570,3575 5570,3420 5500,3350 5175,3350
NetD73_1 on Top Layer "Top Layer-No Net 3" (solid, pour order 77): 3775,4775 3750,4750 3750,4625 3800,4575 3875,4575 3925,4625 4425,4625 4450,4650 4450,4725 4400,4775
GND on Top Layer "Bottom Layer-No Net 1" (solid, pour order 84): 8825,1915 8965,1775 9500,1775 9575,1850 9575,2425 9475,2525 8425,2525 8350,2450 8350,2440 8350,1915
NetCT10_11 on Top Layer "Top Layer-No Net 1" (solid, pour order 86): 7950,7975 9050,7975 9075,7950 9075,7700 9000,7625 7950,7625 7900,7675 7900,7925
C_BU_A on Bottom Layer "Bottom Layer-No Net 2" (solid, pour order 10): 2320,7050 2290,7080 2290,7865 2320,7895 2400,7975 2975,7975 3110,7840 3110,7155 2975,7020 2975,6720 2960,6705 2885,6705 2850,6740 2850,7240 2725,7365 2555,7365 2500,7310 2500,7080 2445,7025 2445,6820 2425,6800 2350,6800 2320,6830
NetCT20_11 on Bottom Layer "Bottom Layer-No Net 6" (solid, pour order 70): 4825,7700 4750,7625 3900,7625 3850,7675 3850,7925 3900,7975 4750,7975 4825,7900
C_BU_B on Bottom Layer "Bottom Layer-No Net 2" (solid, pour order 12): 4950,7600 4925,7625 4800,7625 4775,7600 3900,7600 3775,7475 3775,7080 3815,7040 3815,6800 3840,6775 3915,6775 3940,6800 3940,7050 4000,7110 4000,7260 4065,7325 4265,7325 4360,7230 4360,7130 4275,7045 4275,6600 4325,6550 4325,6365 4270,6310 4270,6290 4450,6290 4485,6325 4485,6420 4435,6470 4435,6705 4465,6735 4465,7020 4545,7100 4875,7100 4950,7175
PGND on Bottom Layer "Bottom Layer-No Net 6" (solid, pour order 60): 4050,3170 4147.5,3072.5 4100,3025 4100,2950 4000,2850 3850,2850 3820,2880 3820,3135 3855,3170
NetQ40_1 on Bottom Layer "Bottom Layer-No Net 2" (solid, pour order 18): 4815,7075 4770,7025 4770,6780 4700,6710 4540,6710 4490,6660 4490,6615 4510,6595 4640,6595 4675,6560 4695,6560 4785,6650 4950,6815 4950,7045 4920,7075
PGND on Bottom Layer "Bottom Layer-No Net 2" (solid, pour order 16): 3570,6600 3570,6450 3610,6410 3610,6335 3625,6320 3670,6320 3675,6325 3785,6325 3795,6315 3855,6315 3865,6325 3865,6430 3835,6460 3725,6570 3725,6720 3710,6735 3710,6975 3710,6990 3675,7025 3675,7200 3570,7305 3390,7305 3390,7235 3550,7075 3550,6620
NetQ20_1 on Bottom Layer "Bottom Layer-No Net 2" (solid, pour order 14): 3145,7180 3145,7115 3150,7110 3190,7110 3275,7025 3275,6765 3175,6665 3175,6615 3200,6590 3340,6590 3360,6570 3385,6570 3425,6610 3425,7010 3255,7180
VBUS on Bottom Layer "Bottom Layer-No Net" (solid, pour order 4): 3550,3305 3505,3260 3505,2965 3305,2765 2705,2765 2645,2825 2645,3030 2450,3225 2150,3525 2150,3725 2200,3775 2795,3775 2850,3720 2850,3275 2925,3200 3085,3200 3315,3430 3475,3430 3550,3355
PGND on Bottom Layer "Bottom Layer-No Net 1" (solid, pour order 8): 2215,6985 2175,7025 2090,7025 1990,6925 1990,6345 2205,6130 2270,6130 2275,6135 2275,6305 2295,6325 2465,6325 2465,6415 2315,6565 2315,6670 2215,6770
C_BA_A on Bottom Layer "Top Layer-No Net 1" (solid, pour order 22): 7500,7075 7560,7135 7560,7740 7325,7975 6525,7975 6300,7750 6300,6855 6620,6535 6620,6290 6580,6250 6580,6185 6590,6175 6680,6175 6700,6195 6700,6355 6720,6375 6805,6375 6850,6420 6850,6460 6775,6535 6775,6575 6525,6825 6525,7150 6900,7525 7275,7525 7350,7450 7350,6875 7375,6850 7470,6850 7500,6880
GND on Bottom Layer "Top Layer-No Net 1" (solid, pour order 24): 7275,7125 7250,7150 7110,7150 7085,7125 7085,6790 7300,6575 7300,6425 7245,6370 7245,6185 7255,6175 7350,6175 7365,6190 7365,6355 7385,6375 7520,6375 7530,6385 7530,6505 7360,6675 7360,6740 7275,6825
NetCT10_11 on Bottom Layer "Top Layer-No Net 1" (solid, pour order 26): 7950,7975 9050,7975 9075,7950 9075,7700 9000,7625 7950,7625 7900,7675 7900,7925
C_BA_B on Bottom Layer "Top Layer-No Net 1" (solid, pour order 28): 7950,7500 7870,7420 7870,6680 7975,6575 7975,6425 7905,6355 7905,6185 7920,6170 8005,6170 8030,6195 8030,6355 8075,6400 8175,6400 8200,6425 8200,6475 8050,6625 8050,6775 8025,6800 8025,7050 8150,7175 8700,7175 8840,7035 8840,6885 8875,6850 8950,6850 9000,6900 9000,7100 9075,7175 9075,7475 9050,7500
GND on Bottom Layer "Top Layer-No Net 1" (solid, pour order 30): 8675,7050 8595,6970 8595,6625 8640,6580 8640,6420 8560,6340 8560,6185 8570,6175 8665,6175 8690,6200 8690,6350 8740,6400 8845,6400 8860,6415 8860,6585 8745,6700 8745,6775 8765,6795 8765,7010 8725,7050
VBAT on Bottom Layer "Top Layer-No Net 1" (solid, pour order 32): 7090,7430 7075,7415 7075,7250 7095,7230 7255,7230 7275,7250 7275,7410 7255,7430
VBAT on Bottom Layer "Top Layer-No Net 1" (solid, pour order 34): 9225,7350 9175,7300 9175,7175 9250,7100 9450,7100 9475,7125 9475,7275 9400,7350
GND on Bottom Layer "Top Layer-No Net 1" (solid, pour order 36): 8200,3770 8790,3180 8790,3045 8910,2925 9250,2925 9475,2700 9475,2440 9495,2420 9475,2400 9475,2375 9425,2325 8175,2325 7900,2600 7900,3170 7075,3995 7075,4150 7875,4950 8750,4950 9225,5425 9275,5475 9275,5650 9225,5700 9225,6055 9055,6225 9055,6490 9225,6660 9225,6975 9250,7000 9725,7000 9905,6820 9905,5020 9505,4620 9050,4165 8345,4165 8200,4020
NetQ150_1 on Bottom Layer "Top Layer-No Net 1" (solid, pour order 38): 9100,7025 9075,7000 9075,6860 8990,6775 8785,6775 8765,6755 8765,6705 8795,6675 9045,6675 9080,6640 9210,6770 9210,7000 9185,7025
Half-BUS on Bottom Layer "Bottom Layer-No Net 3" (solid, pour order 42): 3050,3275 2970,3275 2925,3320 2925,3440 3050,3565 3280,3565 3280,3505
NetR230_1 on Bottom Layer "Bottom Layer-No Net 4" (solid, pour order 52): 9650,2800 9600,2750 9600,2435 9585,2420 9600,2405 9600,1700 9650,1650 9925,1650 9975,1700 9975,2700 9875,2800
GND on Bottom Layer "Bottom Layer-No Net 4" (solid, pour order 54): 6075,4050 6150,3975 6150,3500 6100,3450 5850,3450 5750,3350 5825,3275 7820,3275 7820,4045 7685,4180 6665,4180 6535,4310 5500,4310 5415,4225 5900,4225
VBUS on Bottom Layer "Bottom Layer-No Net 5" (solid, pour order 56): 3375,7900 3325,7850 3325,7775 3350,7750 3600,7750 3625,7775 3625,7850 3575,7900
NetC129_1 on Bottom Layer "Bottom Layer-No Net 5" (solid, pour order 58): 3375,7650 3340,7615 3340,7500 3375,7465 3585,7465 3620,7500 3620,7615 3585,7650
PGND on Bottom Layer "Bottom Layer-No Net 1" (solid, pour order 6): 2125,3875 2370,3875 2370,3920 2295,3995 2170,3995 2105,4060 2105,4335 2105,4595 1930,4770 1930,4935 1475,5390 1475,6000 1575,6100 1825,6100 1925,6200 1925,6850 1850,6925 1100,6925 1025,6850 1025,5000 1400,4625 1400,4400 1025,4025 1025,3250 1250,3025 1300,3025 1300,3150 1350,3200 1585,3200 1750,3365 1750,3500
-5VBU on Bottom Layer "Bottom Layer-No Net 6" (solid, pour order 62): 2515,4140 2515,4030 2505,4020 2395,4020 2180,4020 2125,4075 2125,4450 2175,4500 2280,4500 2305,4475 2392.52,4475 2417.52,4500 2417.52,4517.52 2425,4525 2475,4525 2475,4507.48 2570,4412.48 2570,4380 2725,4225 2725,4165 2540,4165
Half-BUS on Bottom Layer "Bottom Layer-No Net 1" (solid, pour order 81): 4350,3550 4375,3525 4505,3525 4530,3550 4530,3660 4515,3675 4510,3675 4375,3675 4350,3650
Half-BUS on Bottom Layer "Bottom Layer-No Net 1" (solid, pour order 83): 3335,4850 3335,4690 3360,4665 3400,4665 3430,4695 3595,4695 3610,4710 3610,4755 3515,4850

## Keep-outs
Keep-Out Layer:
  lines w200: 4950,1115 4950,1915 4950,4805 4505,5250 2290,5250 2175,5365 2175,5730 2275,5830 4880,5830 5035,5985 5150,6100 5150,6595 5360,6805 5360,7510

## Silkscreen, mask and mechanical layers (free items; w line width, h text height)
Top Overlay:
  text "SEC China" at 4450,1650 h180
  text "6.6KW CLLC Power Stage EVB" at 3050,1450 h180
  text "Ver. 2.1 2021.11. 15" at 3050,1250 h180
Bottom Overlay:
  lines w10: 4100,2275 4200,2375 ; 4175,2375 4200,2375 ; 4200,2350 4200,2375 ; 3800,1875 3800,2275 4200,2275 4200,1875 3800,1875
Mechanical 1:
  lines w10: 1000,1000 10000,1000 10000,8000 1000,8000 1000,1000
  lines w37: 3200,4235 3298.75,4235 3323.75,4210 3381.25,4210 3425.62,4254.38 ; 4275,4255 4450,4255 ; 4725,6260 4725,6525 ; 5505,5840 6000,5840 ; 6500,6280 6565,6345 6565,6520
